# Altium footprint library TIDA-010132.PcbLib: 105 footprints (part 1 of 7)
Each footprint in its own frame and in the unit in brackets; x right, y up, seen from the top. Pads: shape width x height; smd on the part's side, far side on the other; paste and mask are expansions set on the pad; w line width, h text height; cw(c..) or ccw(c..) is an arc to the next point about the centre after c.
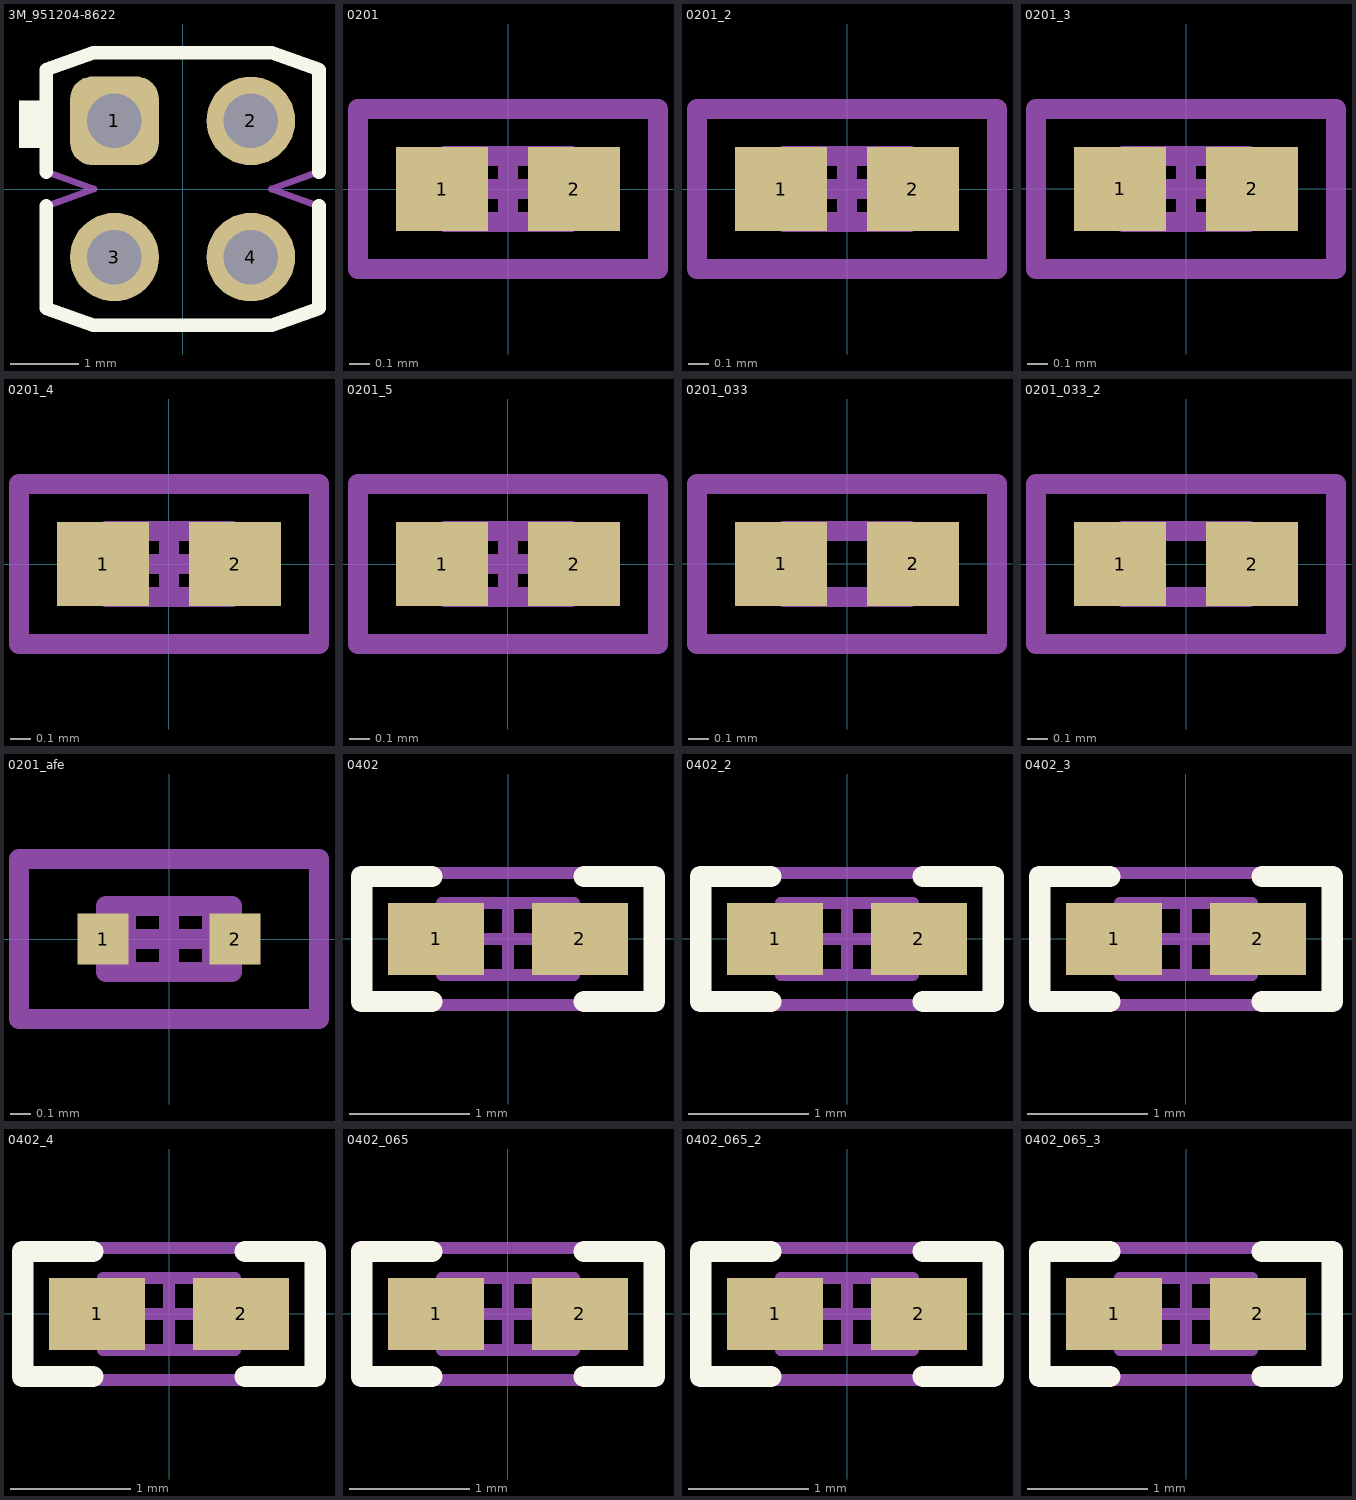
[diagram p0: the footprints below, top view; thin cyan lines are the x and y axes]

## 3M_951204-8622 [mm] "Header, 2mm, 2x2, TH"
height 6.1
pads (4):
  rrect50% 1.3x1.3 hole 0.8: 1(-1,1)
  round 1.3 hole 0.8: 2(1,1) 3(-1,-1) 4(1,-1)
Top Overlay:
  rectangle: -2.4,0.6 -2,1.3
  lines w0.2: -2,-0.25 -2,-1.75 -1.3,-2 1.3,-2 2,-1.75 2,-0.25 ; -2,0.25 -2,1.75 -1.3,2 1.3,2 2,1.75 2,0.25
Mechanical 5:
  lines w0.1: -1.25,-1.25 -1.25,-0.75 ; -1.25,-1.25 -1.1,-1.1 ; -1.25,-1.25 -0.75,-1.25 ; -1.25,-0.75 -1.1,-0.9 ; -1.25,-0.75 -0.75,-0.75 ; -1.25,0.75 -1.25,1.25 ; -1.25,0.75 -1.1,0.9 ; -1.25,0.75 -0.75,0.75 ; -1.25,1.25 -0.75,1.25 ; -1.25,1.25 -1.1,1.1 ; -1.1,-1.1 -0.9,-1.1 ; -1.1,-1.1 -1.1,-0.9 ; -1.1,-0.9 -0.9,-0.9 ; -1.1,0.9 -0.9,0.9 ; -1.1,0.9 -1.1,1.1 ; -1.1,1.1 -0.9,1.1 ; -0.9,-1.1 -0.75,-1.25 ; -0.9,-1.1 -0.9,-0.9 ; -0.9,-0.9 -0.75,-0.75 ; -0.9,0.9 -0.9,1.1 ; -0.9,0.9 -0.75,0.75 ; -0.9,1.1 -0.75,1.25 ; -0.75,-1.25 -0.75,-0.75 ; -0.75,0.75 -0.75,1.25 ; 0.75,-1.25 1.25,-1.25 ; 0.75,-1.25 0.9,-1.1 ; 0.75,-1.25 0.75,-0.75 ; 0.75,-0.75 0.9,-0.9 ; 0.75,-0.75 1.25,-0.75 ; 0.75,0.75 1.25,0.75 ; 0.75,0.75 0.75,1.25 ; 0.75,0.75 0.9,0.9 ; 0.75,1.25 1.25,1.25 ; 0.75,1.25 0.9,1.1 ; 0.9,-1.1 1.1,-1.1 ; 0.9,-1.1 0.9,-0.9 ; 0.9,-0.9 1.1,-0.9 ; 0.9,0.9 1.1,0.9 ; 0.9,0.9 0.9,1.1 ; 0.9,1.1 1.1,1.1 ; 1.1,-1.1 1.1,-0.9 ; 1.1,-1.1 1.25,-1.25 ; 1.1,-0.9 1.25,-0.75 ; 1.1,0.9 1.25,0.75 ; 1.1,0.9 1.1,1.1 ; 1.1,1.1 1.25,1.25 ; 1.25,-1.25 1.25,-0.75 ; 1.25,0.75 1.25,1.25 ; -2,-1.75 -1.3,-2 1.3,-2 2,-1.75 2,-0.25 1.3,0 2,0.25 2,1.75 1.3,2 -1.3,2 -2,1.75 -2,0.25 -1.3,0 -2,-0.25 -2,-1.75
  text ".Designator" at -0.7,-0.1 h0.46
3D body "951204-8622.stp": height 5.9, standoff -2.4, extent -2,-2 2,2

## 0201 [mm] "Data from Kemet datasheet CC101_COM dated 7/28/11"
height 0.26
pads (2):
  rect 0.46x0.42 smd mask+0.048: 1(-0.33,0) 2(0.33,0)
Mechanical 5:
  lines w0.1: -0.75,-0.4 -0.75,0.4 0.75,0.4 0.75,-0.4 -0.75,-0.4
  text ".Designator" at -0.66,-0.178 h0.46
Mechanical 13:
  lines w0.1: -0.215,-0.165 -0.215,0.165 ; 0.215,-0.165 0.215,0.165 ; -0.315,-0.165 0.315,-0.165 0.315,0.165 -0.315,0.165 -0.315,-0.165
Mechanical 15:
  lines w0.1: -0.165,0 0.165,0 ; 0,-0.165 0,0.165 ; -0.75,-0.4 0.75,-0.4 0.75,0.4 -0.75,0.4 -0.75,-0.4
3D body: height 0.26, standoff 0, extent 0.216,-0.164 0.314,0.164
3D body: height 0.26, standoff 0, extent -0.314,-0.164 -0.216,0.164
3D body: height 0.26, standoff 0, extent -0.214,-0.164 0.214,0.164

## 0201_2 [mm]
pads (2):
  rect 0.46x0.42 smd mask+0.048: 1(-0.33,0) 2(0.33,0)
Mechanical 5:
  lines w0.1: -0.75,-0.4 -0.75,0.4 0.75,0.4 0.75,-0.4 -0.75,-0.4
  text ".Designator" at -0.66,-0.178 h0.46
Mechanical 13:
  lines w0.1: -0.215,-0.165 -0.215,0.165 ; 0.215,-0.165 0.215,0.165 ; -0.315,-0.165 0.315,-0.165 0.315,0.165 -0.315,0.165 -0.315,-0.165
Mechanical 15:
  lines w0.1: -0.165,0 0.165,0 ; 0,-0.165 0,0.165 ; -0.75,-0.4 0.75,-0.4 0.75,0.4 -0.75,0.4 -0.75,-0.4
3D body: height 0.26, standoff 0, extent 0.216,-0.164 0.314,0.164
3D body: height 0.26, standoff 0, extent -0.214,-0.164 0.214,0.164
3D body: height 0.26, standoff 0, extent -0.314,-0.164 -0.216,0.164

## 0201_3 [mm]
pads (2):
  rect 0.46x0.42 smd mask+0.048: 1(-0.33,0) 2(0.33,0)
Mechanical 5:
  lines w0.1: -0.75,-0.4 -0.75,0.4 0.75,0.4 0.75,-0.4 -0.75,-0.4
  text ".Designator" at -0.66,-0.178 h0.46
Mechanical 13:
  lines w0.1: -0.215,-0.165 -0.215,0.165 ; 0.215,-0.165 0.215,0.165 ; -0.315,-0.165 0.315,-0.165 0.315,0.165 -0.315,0.165 -0.315,-0.165
Mechanical 15:
  lines w0.1: -0.165,0 0.165,0 ; 0,-0.165 0,0.165 ; -0.75,-0.4 0.75,-0.4 0.75,0.4 -0.75,0.4 -0.75,-0.4
3D body: height 0.26, standoff 0, extent 0.216,-0.164 0.314,0.164
3D body: height 0.26, standoff 0, extent -0.314,-0.164 -0.216,0.164
3D body: height 0.26, standoff 0, extent -0.214,-0.164 0.214,0.164

## 0201_4 [mm]
pads (2):
  rect 0.46x0.42 smd mask+0.048: 1(-0.33,0) 2(0.33,0)
Mechanical 5:
  lines w0.1: -0.75,-0.4 0.75,-0.4 0.75,0.4 -0.75,0.4 -0.75,-0.4
  text ".Designator" at -0.66,-0.178 h0.46
Mechanical 13:
  lines w0.1: -0.215,-0.165 -0.215,0.165 ; 0.215,-0.165 0.215,0.165 ; -0.315,-0.165 -0.315,0.165 0.315,0.165 0.315,-0.165 -0.315,-0.165
Mechanical 15:
  lines w0.1: -0.165,0 0.165,0 ; 0,-0.165 0,0.165 ; -0.75,-0.4 -0.75,0.4 0.75,0.4 0.75,-0.4 -0.75,-0.4
3D body: height 0.26, standoff 0, extent -0.314,-0.164 -0.216,0.164
3D body: height 0.26, standoff 0, extent 0.216,-0.164 0.314,0.164
3D body: height 0.26, standoff 0, extent -0.214,-0.164 0.214,0.164

## 0201_5 [mm]
pads (2):
  rect 0.46x0.42 smd mask+0.048: 1(-0.33,0) 2(0.33,0)
Mechanical 5:
  lines w0.1: -0.75,-0.4 -0.75,0.4 0.75,0.4 0.75,-0.4 -0.75,-0.4
  text ".Designator" at -0.66,-0.178 h0.46
Mechanical 13:
  lines w0.1: -0.215,-0.165 -0.215,0.165 ; 0.215,-0.165 0.215,0.165 ; -0.315,-0.165 0.315,-0.165 0.315,0.165 -0.315,0.165 -0.315,-0.165
Mechanical 15:
  lines w0.1: -0.165,0 0.165,0 ; 0,-0.165 0,0.165 ; -0.75,-0.4 0.75,-0.4 0.75,0.4 -0.75,0.4 -0.75,-0.4
3D body: height 0.26, standoff 0, extent 0.216,-0.164 0.314,0.164
3D body: height 0.26, standoff 0, extent -0.314,-0.164 -0.216,0.164
3D body: height 0.26, standoff 0, extent -0.214,-0.164 0.214,0.164

## 0201_033 [mm] "SMD, 2-Leads, Height 0.33mm"
height 0.33
pads (2):
  rect 0.46x0.42 smd mask+0.048: 1(-0.33,0) 2(0.33,0)
Mechanical 5:
  lines w0.1: -0.75,-0.4 0.75,-0.4 0.75,0.4 -0.75,0.4 -0.75,-0.4
  text ".Designator" at -0.66,-0.178 h0.46
Mechanical 13:
  lines w0.1: -0.215,-0.165 -0.215,0.165 ; 0.215,-0.165 0.215,0.165 ; -0.315,-0.165 -0.315,0.165 0.315,0.165 0.315,-0.165 -0.315,-0.165
3D body: height 0.33, standoff 0, extent -0.314,-0.164 -0.216,0.164
3D body: height 0.33, standoff 0, extent 0.216,-0.164 0.314,0.164
3D body: height 0.33, standoff 0, extent -0.214,-0.164 0.214,0.164

## 0201_033_2 [mm]
pads (2):
  rect 0.46x0.42 smd mask+0.048: 1(-0.33,0) 2(0.33,0)
Mechanical 5:
  lines w0.1: -0.75,-0.4 -0.75,0.4 0.75,0.4 0.75,-0.4 -0.75,-0.4
  text ".Designator" at -0.66,-0.178 h0.46
Mechanical 13:
  lines w0.1: -0.215,-0.165 -0.215,0.165 ; 0.215,-0.165 0.215,0.165 ; -0.315,-0.165 0.315,-0.165 0.315,0.165 -0.315,0.165 -0.315,-0.165
3D body: height 0.33, standoff 0, extent 0.216,-0.164 0.314,0.164
3D body: height 0.33, standoff 0, extent -0.314,-0.164 -0.216,0.164
3D body: height 0.33, standoff 0, extent -0.214,-0.164 0.214,0.164

## 0201_afe [mil] "0201_afe"
pads (2):
  rect 10x10 smd mask+1.9: 1(-12.99,0) 2(12.99,0)
Mechanical 5:
  lines w3.94: -29.53,-15.75 -29.53,15.75 29.53,15.75 29.53,-15.75 -29.53,-15.75
  text ".Designator" at -26,-7 h18
Mechanical 13:
  lines w3.94: -8.46,-6.5 -8.46,6.5 ; 8.46,-6.5 8.46,6.5 ; -12.4,-6.5 12.4,-6.5 12.4,6.5 -12.4,6.5 -12.4,-6.5
Mechanical 15:
  lines w3.94: -6.5,0 6.5,0 ; 0,-6.5 0,6.5 ; -29.53,-15.75 29.53,-15.75 29.53,15.75 -29.53,15.75 -29.53,-15.75
3D body: height 10.24, standoff 0, extent 8.48,-6.48 12.38,6.48
3D body: height 10.24, standoff 0, extent -12.38,-6.48 -8.48,6.48
3D body: height 10.24, standoff 0, extent -8.44,-6.48 8.44,6.48

## 0402 [mm] "0402 from SM-752 data"
height 0.6
pads (2):
  rect 0.8x0.6 smd: 1(-0.6,0) 2(0.6,0)
Top Overlay:
  lines w0.178: -0.635,-0.521 -1.219,-0.521 -1.219,0.521 -0.635,0.521 ; 0.635,-0.521 1.219,-0.521 1.219,0.521 0.635,0.521
Mechanical 5:
  lines w0.1: -1.25,-0.55 -1.25,0.55 1.25,0.55 1.25,-0.55 -1.25,-0.55
  text ".Designator" at -1.117,-0.305 h0.46
Mechanical 13:
  lines w0.1: -0.35,-0.3 -0.35,0.3 ; 0.35,-0.3 0.35,0.3 ; -0.55,-0.3 0.55,-0.3 0.55,0.3 -0.55,0.3 -0.55,-0.3
Mechanical 15:
  lines w0.1: -0.3,0 0.3,0 ; 0,-0.3 0,0.3 ; -1.25,-0.55 1.25,-0.55 1.25,0.55 -1.25,0.55 -1.25,-0.55
3D body: height 0.6, standoff 0, extent 0.351,-0.299 0.549,0.299
3D body: height 0.6, standoff 0, extent -0.349,-0.299 0.349,0.299
3D body: height 0.6, standoff 0, extent -0.549,-0.299 -0.351,0.299

## 0402_2 [mm]
pads (2):
  rect 0.8x0.6 smd: 1(-0.6,0) 2(0.6,0)
Top Overlay:
  lines w0.178: -0.635,-0.521 -1.219,-0.521 -1.219,0.521 -0.635,0.521 ; 0.635,-0.521 1.219,-0.521 1.219,0.521 0.635,0.521
Mechanical 5:
  lines w0.1: -1.25,-0.55 -1.25,0.55 1.25,0.55 1.25,-0.55 -1.25,-0.55
  text ".Designator" at -1.117,-0.305 h0.46
Mechanical 13:
  lines w0.1: -0.35,-0.3 -0.35,0.3 ; 0.35,-0.3 0.35,0.3 ; -0.55,-0.3 0.55,-0.3 0.55,0.3 -0.55,0.3 -0.55,-0.3
Mechanical 15:
  lines w0.1: -0.3,0 0.3,0 ; 0,-0.3 0,0.3 ; -1.25,-0.55 1.25,-0.55 1.25,0.55 -1.25,0.55 -1.25,-0.55
3D body: height 0.6, standoff 0, extent 0.351,-0.299 0.549,0.299
3D body: height 0.6, standoff 0, extent -0.349,-0.299 0.349,0.299
3D body: height 0.6, standoff 0, extent -0.549,-0.299 -0.351,0.299

## 0402_3 [mm]
pads (2):
  rect 0.8x0.6 smd: 1(-0.6,0) 2(0.6,0)
Top Overlay:
  lines w0.178: -0.635,-0.521 -1.219,-0.521 -1.219,0.521 -0.635,0.521 ; 0.635,-0.521 1.219,-0.521 1.219,0.521 0.635,0.521
Mechanical 5:
  lines w0.1: -1.25,-0.55 1.25,-0.55 1.25,0.55 -1.25,0.55 -1.25,-0.55
  text ".Designator" at -1.037,-0.328 h0.46
Mechanical 13:
  lines w0.1: -0.35,-0.3 -0.35,0.3 ; 0.35,-0.3 0.35,0.3 ; -0.55,-0.3 -0.55,0.3 0.55,0.3 0.55,-0.3 -0.55,-0.3
Mechanical 15:
  lines w0.1: -0.3,0 0.3,0 ; 0,-0.3 0,0.3 ; -1.25,-0.55 -1.25,0.55 1.25,0.55 1.25,-0.55 -1.25,-0.55
3D body: height 0.6, standoff 0, extent -0.549,-0.299 -0.351,0.299
3D body: height 0.6, standoff 0, extent -0.349,-0.299 0.349,0.299
3D body: height 0.6, standoff 0, extent 0.351,-0.299 0.549,0.299

## 0402_4 [mm]
pads (2):
  rect 0.8x0.6 smd: 1(-0.6,0) 2(0.6,0)
Top Overlay:
  lines w0.178: -0.635,-0.521 -1.219,-0.521 -1.219,0.521 -0.635,0.521 ; 0.635,-0.521 1.219,-0.521 1.219,0.521 0.635,0.521
Mechanical 5:
  lines w0.1: -1.25,-0.55 -1.25,0.55 1.25,0.55 1.25,-0.55 -1.25,-0.55
  text ".Designator" at -1.117,-0.305 h0.46
Mechanical 13:
  lines w0.1: -0.35,-0.3 -0.35,0.3 ; 0.35,-0.3 0.35,0.3 ; -0.55,-0.3 0.55,-0.3 0.55,0.3 -0.55,0.3 -0.55,-0.3
Mechanical 15:
  lines w0.1: -0.3,0 0.3,0 ; 0,-0.3 0,0.3 ; -1.25,-0.55 1.25,-0.55 1.25,0.55 -1.25,0.55 -1.25,-0.55
3D body: height 0.6, standoff 0, extent 0.351,-0.299 0.549,0.299
3D body: height 0.6, standoff 0, extent -0.349,-0.299 0.349,0.299
3D body: height 0.6, standoff 0, extent -0.549,-0.299 -0.351,0.299

## 0402_065 [mm] "0402"
height 0.65
pads (2):
  rect 0.8x0.6 smd: 1(-0.6,0) 2(0.6,0)
Top Overlay:
  lines w0.178: -0.635,-0.521 -1.219,-0.521 -1.219,0.521 -0.635,0.521 ; 0.635,-0.521 1.219,-0.521 1.219,0.521 0.635,0.521
Mechanical 5:
  lines w0.1: -1.25,-0.55 1.25,-0.55 1.25,0.55 -1.25,0.55 -1.25,-0.55
  text ".Designator" at -1.117,-0.305 h0.46
Mechanical 13:
  lines w0.1: -0.35,-0.3 -0.35,0.3 ; 0.35,-0.3 0.35,0.3 ; -0.55,-0.3 -0.55,0.3 0.55,0.3 0.55,-0.3 -0.55,-0.3
Mechanical 15:
  lines w0.1: -0.3,0 0.3,0 ; 0,-0.3 0,0.3 ; -1.25,-0.55 -1.25,0.55 1.25,0.55 1.25,-0.55 -1.25,-0.55
3D body: height 0.65, standoff 0, extent -0.549,-0.299 -0.351,0.299
3D body: height 0.65, standoff 0, extent -0.349,-0.299 0.349,0.299
3D body: height 0.65, standoff 0, extent 0.351,-0.299 0.549,0.299

## 0402_065_2 [mm]
pads (2):
  rect 0.8x0.6 smd: 1(-0.6,0) 2(0.6,0)
Top Overlay:
  lines w0.178: -0.635,-0.521 -1.219,-0.521 -1.219,0.521 -0.635,0.521 ; 0.635,-0.521 1.219,-0.521 1.219,0.521 0.635,0.521
Mechanical 5:
  lines w0.1: -1.25,-0.55 -1.25,0.55 1.25,0.55 1.25,-0.55 -1.25,-0.55
  text ".Designator" at 0.806,0.155 h0.46
Mechanical 13:
  lines w0.1: -0.35,-0.3 -0.35,0.3 ; 0.35,-0.3 0.35,0.3 ; -0.55,-0.3 0.55,-0.3 0.55,0.3 -0.55,0.3 -0.55,-0.3
Mechanical 15:
  lines w0.1: -0.3,0 0.3,0 ; 0,-0.3 0,0.3 ; -1.25,-0.55 1.25,-0.55 1.25,0.55 -1.25,0.55 -1.25,-0.55
3D body: height 0.65, standoff 0, extent 0.351,-0.299 0.549,0.299
3D body: height 0.65, standoff 0, extent -0.349,-0.299 0.349,0.299
3D body: height 0.65, standoff 0, extent -0.549,-0.299 -0.351,0.299

## 0402_065_3 [mm]
pads (2):
  rect 0.8x0.6 smd: 1(-0.6,0) 2(0.6,0)
Top Overlay:
  lines w0.178: -0.635,-0.521 -1.219,-0.521 -1.219,0.521 -0.635,0.521 ; 0.635,-0.521 1.219,-0.521 1.219,0.521 0.635,0.521
Mechanical 5:
  lines w0.1: -1.25,-0.55 1.25,-0.55 1.25,0.55 -1.25,0.55 -1.25,-0.55
  text ".Designator" at -1.117,-0.305 h0.46
Mechanical 13:
  lines w0.1: -0.35,-0.3 -0.35,0.3 ; 0.35,-0.3 0.35,0.3 ; -0.55,-0.3 -0.55,0.3 0.55,0.3 0.55,-0.3 -0.55,-0.3
Mechanical 15:
  lines w0.1: -0.3,0 0.3,0 ; 0,-0.3 0,0.3 ; -1.25,-0.55 -1.25,0.55 1.25,0.55 1.25,-0.55 -1.25,-0.55
3D body: height 0.65, standoff 0, extent -0.549,-0.299 -0.351,0.299
3D body: height 0.65, standoff 0, extent -0.349,-0.299 0.349,0.299
3D body: height 0.65, standoff 0, extent 0.351,-0.299 0.549,0.299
